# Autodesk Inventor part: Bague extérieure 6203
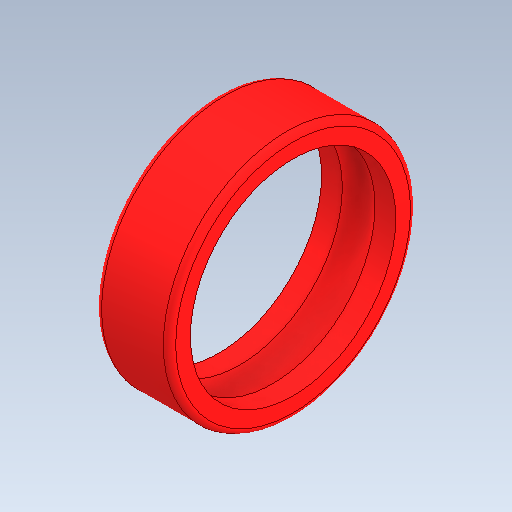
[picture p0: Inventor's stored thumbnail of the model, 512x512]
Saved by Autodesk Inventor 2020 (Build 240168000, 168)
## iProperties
Created: 2003-06
Part Number: Bague extérieure 6203
Material: Générique
Document SubType Name: Modeling
Designer: Bruno
Density: 1 g/cm^3
Appearance: Par défaut
Author: Bruno
Sending System: SolidWorks 2011
Last Author: frederic
Last Saved: 2012-02-20
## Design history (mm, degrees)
feature "Base-Révolution"
node "Solide1"
